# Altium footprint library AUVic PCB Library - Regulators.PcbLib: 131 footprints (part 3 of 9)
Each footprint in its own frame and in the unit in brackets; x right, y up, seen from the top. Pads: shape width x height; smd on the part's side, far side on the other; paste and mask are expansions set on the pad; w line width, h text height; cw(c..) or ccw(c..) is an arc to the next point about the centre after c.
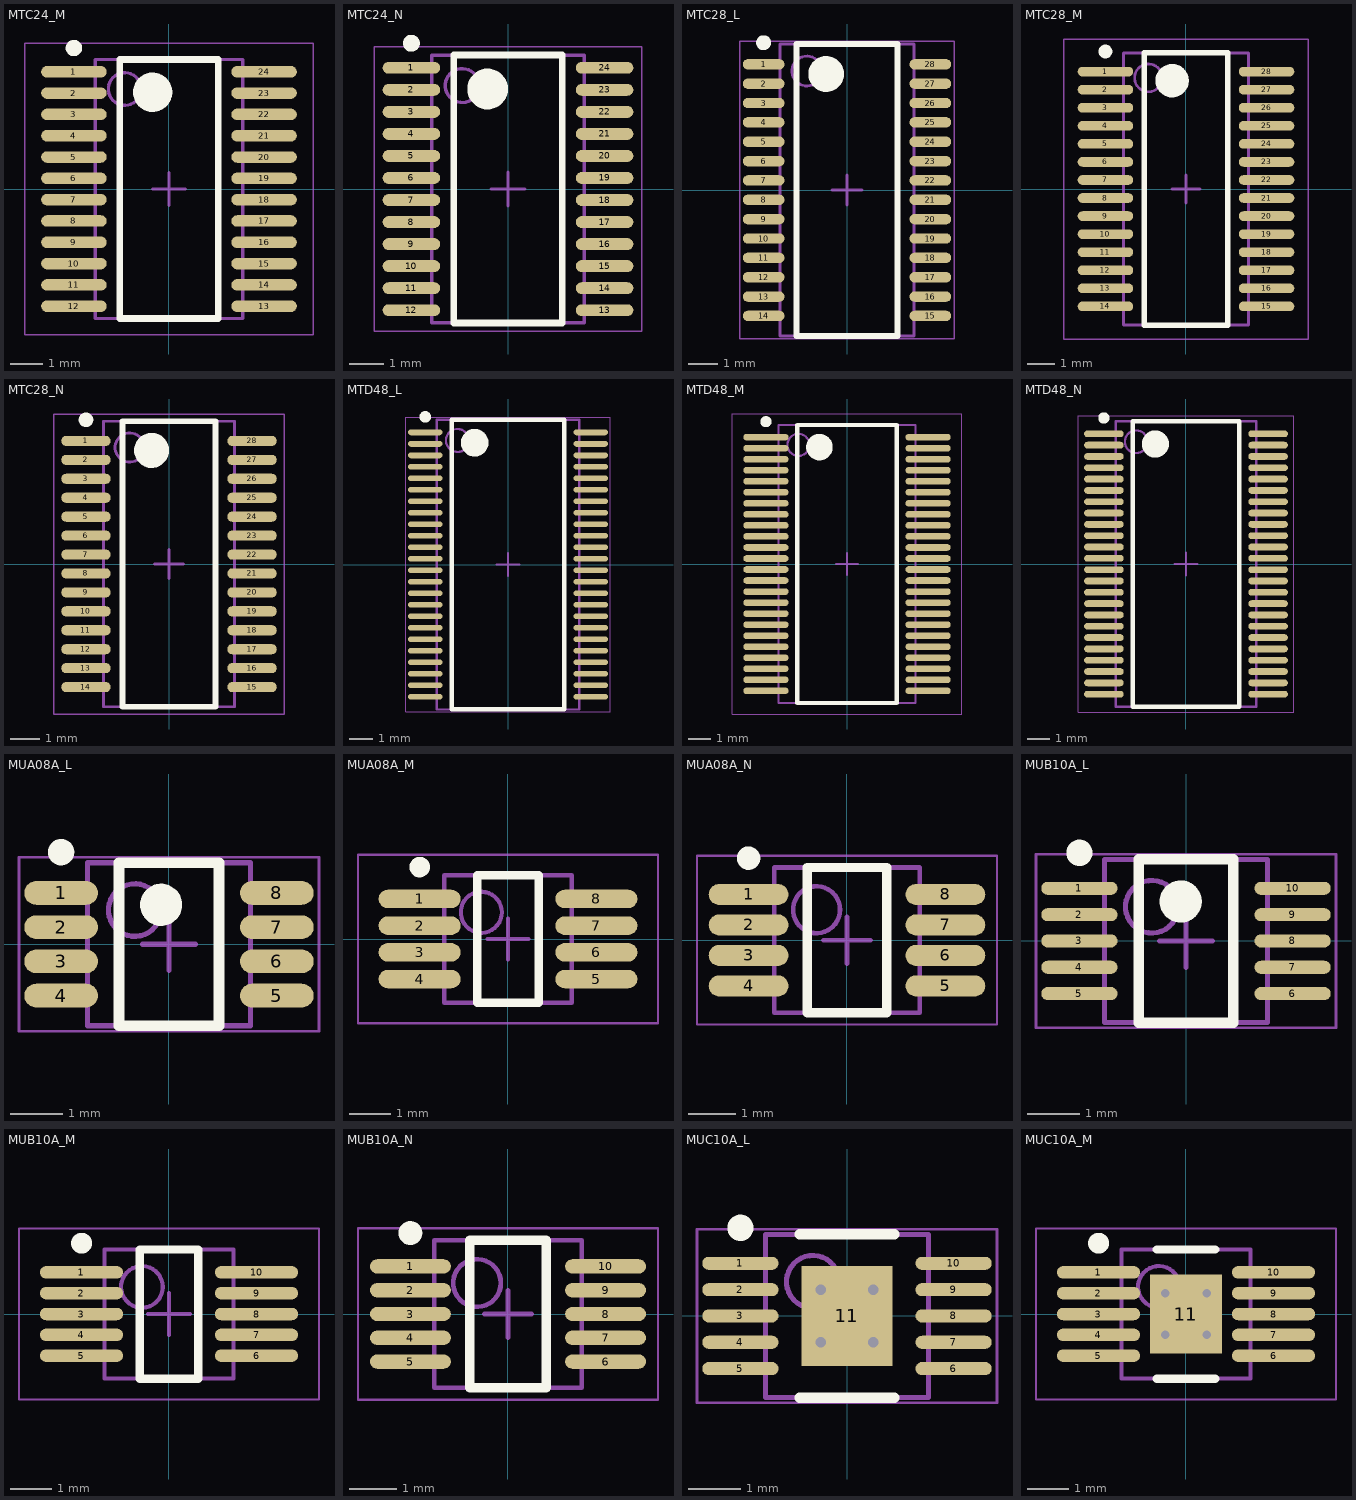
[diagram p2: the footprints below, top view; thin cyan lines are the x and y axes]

## MTC24_M [mm] "TSOP, 24-Leads, Body 7.8x4.4mm, Pitch 0.65mm, IPC Low Density"
height 1.1
pads (24):
  oval 2x0.35 smd: 1(-2.9,3.575) 2(-2.9,2.925) 3(-2.9,2.275) 4(-2.9,1.625) 5(-2.9,0.975) 6(-2.9,0.325) 7(-2.9,-0.325) 8(-2.9,-0.975) 9(-2.9,-1.625) 10(-2.9,-2.275) 11(-2.9,-2.925) 12(-2.9,-3.575) 13(2.9,-3.575) 14(2.9,-2.925) 15(2.9,-2.275) 16(2.9,-1.625) 17(2.9,-0.975) 18(2.9,-0.325) 19(2.9,0.325) 20(2.9,0.975) 21(2.9,1.625) 22(2.9,2.275) 23(2.9,2.925) 24(2.9,3.575)
Top Overlay:
  circle w0.6: c-0.5,2.95 r0.3
  circle w0.25: c-2.9,4.3 r0.125
  lines w0.2: -1.5,-3.95 1.5,-3.95 1.5,3.95 -1.5,3.95 -1.5,-3.95
Mechanical 13:
  circle w0.1: c-1.35,3.05 r0.5
  lines w0.1: -2.25,-3.95 2.25,-3.95 2.25,3.95 -2.25,3.95 -2.25,-3.95
Mechanical 15:
  lines w0.05: -4.4,-4.45 4.4,-4.45 4.4,4.45 -4.4,4.45 -4.4,-4.45
  lines w0.1: -0.5,0 0.5,0 ; 0,-0.5 0,0.5
3D body: height 1.1, standoff 0.05, extent -2.25,-3.95 2.25,3.95

## MTC24_N [mm] "TSOP, 24-Leads, Body 7.8x4.4mm, Pitch 0.65mm, IPC Medium Density"
height 1.1
pads (24):
  oval 1.7x0.35 smd: 1(-2.85,3.575) 2(-2.85,2.925) 3(-2.85,2.275) 4(-2.85,1.625) 5(-2.85,0.975) 6(-2.85,0.325) 7(-2.85,-0.325) 8(-2.85,-0.975) 9(-2.85,-1.625) 10(-2.85,-2.275) 11(-2.85,-2.925) 12(-2.85,-3.575) 13(2.85,-3.575) 14(2.85,-2.925) 15(2.85,-2.275) 16(2.85,-1.625) 17(2.85,-0.975) 18(2.85,-0.325) 19(2.85,0.325) 20(2.85,0.975) 21(2.85,1.625) 22(2.85,2.275) 23(2.85,2.925) 24(2.85,3.575)
Top Overlay:
  circle w0.6: c-0.6,2.95 r0.3
  circle w0.25: c-2.85,4.3 r0.125
  lines w0.2: -1.6,-3.95 1.6,-3.95 1.6,3.95 -1.6,3.95 -1.6,-3.95
Mechanical 13:
  circle w0.1: c-1.35,3.05 r0.5
  lines w0.1: -2.25,-3.95 2.25,-3.95 2.25,3.95 -2.25,3.95 -2.25,-3.95
Mechanical 15:
  lines w0.05: -3.95,-4.2 3.95,-4.2 3.95,4.2 -3.95,4.2 -3.95,-4.2
  lines w0.1: -0.5,0 0.5,0 ; 0,-0.5 0,0.5
3D body: height 1.1, standoff 0.05, extent -2.25,-3.95 2.25,3.95

## MTC28_L [mm] "TSOP, 28-Leads, Body 9.7x4.4mm, Pitch 0.65mm, IPC High Density"
height 1.1
pads (28):
  oval 1.4x0.35 smd: 1(-2.8,4.225) 2(-2.8,3.575) 3(-2.8,2.925) 4(-2.8,2.275) 5(-2.8,1.625) 6(-2.8,0.975) 7(-2.8,0.325) 8(-2.8,-0.325) 9(-2.8,-0.975) 10(-2.8,-1.625) 11(-2.8,-2.275) 12(-2.8,-2.925) 13(-2.8,-3.575) 14(-2.8,-4.225) 15(2.8,-4.225) 16(2.8,-3.575) 17(2.8,-2.925) 18(2.8,-2.275) 19(2.8,-1.625) 20(2.8,-0.975) 21(2.8,-0.325) 22(2.8,0.325) 23(2.8,0.975) 24(2.8,1.625) 25(2.8,2.275) 26(2.8,2.925) 27(2.8,3.575) 28(2.8,4.225)
Top Overlay:
  circle w0.25: c-2.8,4.95 r0.125
  circle w0.6: c-0.7,3.9 r0.3
  lines w0.2: -1.7,-4.9 -1.7,4.9 1.7,4.9 1.7,-4.9 -1.7,-4.9
Mechanical 13:
  circle w0.1: c-1.35,4 r0.5
  lines w0.1: -2.25,-4.9 -2.25,4.9 2.25,4.9 2.25,-4.9 -2.25,-4.9
Mechanical 15:
  lines w0.05: -3.6,-5 -3.6,5 3.6,5 3.6,-5 -3.6,-5
  lines w0.1: -0.5,0 0.5,0 ; 0,-0.5 0,0.5
3D body: height 1.1, standoff 0.05, extent -2.25,-4.9 2.25,4.9

## MTC28_M [mm] "TSOP, 28-Leads, Body 9.7x4.4mm, Pitch 0.65mm, IPC Low Density"
height 1.1
pads (28):
  oval 2x0.35 smd: 1(-2.9,4.225) 2(-2.9,3.575) 3(-2.9,2.925) 4(-2.9,2.275) 5(-2.9,1.625) 6(-2.9,0.975) 7(-2.9,0.325) 8(-2.9,-0.325) 9(-2.9,-0.975) 10(-2.9,-1.625) 11(-2.9,-2.275) 12(-2.9,-2.925) 13(-2.9,-3.575) 14(-2.9,-4.225) 15(2.9,-4.225) 16(2.9,-3.575) 17(2.9,-2.925) 18(2.9,-2.275) 19(2.9,-1.625) 20(2.9,-0.975) 21(2.9,-0.325) 22(2.9,0.325) 23(2.9,0.975) 24(2.9,1.625) 25(2.9,2.275) 26(2.9,2.925) 27(2.9,3.575) 28(2.9,4.225)
Top Overlay:
  circle w0.25: c-2.9,4.95 r0.125
  circle w0.6: c-0.5,3.9 r0.3
  lines w0.2: -1.5,-4.9 -1.5,4.9 1.5,4.9 1.5,-4.9 -1.5,-4.9
Mechanical 13:
  circle w0.1: c-1.35,4 r0.5
  lines w0.1: -2.25,-4.9 -2.25,4.9 2.25,4.9 2.25,-4.9 -2.25,-4.9
Mechanical 15:
  lines w0.05: -4.4,-5.4 -4.4,5.4 4.4,5.4 4.4,-5.4 -4.4,-5.4
  lines w0.1: -0.5,0 0.5,0 ; 0,-0.5 0,0.5
3D body: height 1.1, standoff 0.05, extent -2.25,-4.9 2.25,4.9

## MTC28_N [mm] "TSOP, 28-Leads, Body 9.7x4.4mm, Pitch 0.65mm, IPC Medium Density"
height 1.1
pads (28):
  oval 1.7x0.35 smd: 1(-2.85,4.225) 2(-2.85,3.575) 3(-2.85,2.925) 4(-2.85,2.275) 5(-2.85,1.625) 6(-2.85,0.975) 7(-2.85,0.325) 8(-2.85,-0.325) 9(-2.85,-0.975) 10(-2.85,-1.625) 11(-2.85,-2.275) 12(-2.85,-2.925) 13(-2.85,-3.575) 14(-2.85,-4.225) 15(2.85,-4.225) 16(2.85,-3.575) 17(2.85,-2.925) 18(2.85,-2.275) 19(2.85,-1.625) 20(2.85,-0.975) 21(2.85,-0.325) 22(2.85,0.325) 23(2.85,0.975) 24(2.85,1.625) 25(2.85,2.275) 26(2.85,2.925) 27(2.85,3.575) 28(2.85,4.225)
Top Overlay:
  circle w0.25: c-2.85,4.95 r0.125
  circle w0.6: c-0.6,3.9 r0.3
  lines w0.2: -1.6,-4.9 -1.6,4.9 1.6,4.9 1.6,-4.9 -1.6,-4.9
Mechanical 13:
  circle w0.1: c-1.35,4 r0.5
  lines w0.1: -2.25,-4.9 -2.25,4.9 2.25,4.9 2.25,-4.9 -2.25,-4.9
Mechanical 15:
  lines w0.05: -3.95,-5.15 -3.95,5.15 3.95,5.15 3.95,-5.15 -3.95,-5.15
  lines w0.1: -0.5,0 0.5,0 ; 0,-0.5 0,0.5
3D body: height 1.1, standoff 0.05, extent -2.25,-4.9 2.25,4.9

## MTD48_L [mm] "TSSOP, 48-Leads, Body 12.5x6.1mm, Pitch 0.5mm, IPC High Density"
height 1.1
pads (48):
  oval 1.5x0.25 smd: 1(-3.6,5.75) 2(-3.6,5.25) 3(-3.6,4.75) 4(-3.6,4.25) 5(-3.6,3.75) 6(-3.6,3.25) 7(-3.6,2.75) 8(-3.6,2.25) 9(-3.6,1.75) 10(-3.6,1.25) 11(-3.6,0.75) 12(-3.6,0.25) 13(-3.6,-0.25) 14(-3.6,-0.75) 15(-3.6,-1.25) 16(-3.6,-1.75) 17(-3.6,-2.25) 18(-3.6,-2.75) 19(-3.6,-3.25) 20(-3.6,-3.75) 21(-3.6,-4.25) 22(-3.6,-4.75) 23(-3.6,-5.25) 24(-3.6,-5.75) 25(3.6,-5.75) 26(3.6,-5.25) 27(3.6,-4.75) 28(3.6,-4.25) 29(3.6,-3.75) 30(3.6,-3.25) 31(3.6,-2.75) 32(3.6,-2.25) 33(3.6,-1.75) 34(3.6,-1.25) 35(3.6,-0.75) 36(3.6,-0.25) 37(3.6,0.25) 38(3.6,0.75) 39(3.6,1.25) 40(3.6,1.75) 41(3.6,2.25) 42(3.6,2.75) 43(3.6,3.25) 44(3.6,3.75) 45(3.6,4.25) 46(3.6,4.75) 47(3.6,5.25) 48(3.6,5.75)
Top Overlay:
  circle w0.6: c-1.45,5.3 r0.3
  circle w0.25: c-3.6,6.425 r0.125
  lines w0.2: -2.45,-6.3 2.45,-6.3 2.45,6.3 -2.45,6.3 -2.45,-6.3
Mechanical 13:
  circle w0.1: c-2.2,5.4 r0.5
  lines w0.1: -3.1,-6.3 3.1,-6.3 3.1,6.3 -3.1,6.3 -3.1,-6.3
Mechanical 15:
  lines w0.05: -4.45,-6.4 4.45,-6.4 4.45,6.4 -4.45,6.4 -4.45,-6.4
  lines w0.1: -0.5,0 0.5,0 ; 0,-0.5 0,0.5
3D body: height 1.1, standoff 0.05, extent -3.1,-6.3 3.1,6.3

## MTD48_M [mm] "TSSOP, 48-Leads, Body 12.5x6.1mm, Pitch 0.5mm, IPC Low Density"
height 1.1
pads (48):
  oval 2.05x0.3 smd: 1(-3.675,5.75) 2(-3.675,5.25) 3(-3.675,4.75) 4(-3.675,4.25) 5(-3.675,3.75) 6(-3.675,3.25) 7(-3.675,2.75) 8(-3.675,2.25) 9(-3.675,1.75) 10(-3.675,1.25) 11(-3.675,0.75) 12(-3.675,0.25) 13(-3.675,-0.25) 14(-3.675,-0.75) 15(-3.675,-1.25) 16(-3.675,-1.75) 17(-3.675,-2.25) 18(-3.675,-2.75) 19(-3.675,-3.25) 20(-3.675,-3.75) 21(-3.675,-4.25) 22(-3.675,-4.75) 23(-3.675,-5.25) 24(-3.675,-5.75) 25(3.675,-5.75) 26(3.675,-5.25) 27(3.675,-4.75) 28(3.675,-4.25) 29(3.675,-3.75) 30(3.675,-3.25) 31(3.675,-2.75) 32(3.675,-2.25) 33(3.675,-1.75) 34(3.675,-1.25) 35(3.675,-0.75) 36(3.675,-0.25) 37(3.675,0.25) 38(3.675,0.75) 39(3.675,1.25) 40(3.675,1.75) 41(3.675,2.25) 42(3.675,2.75) 43(3.675,3.25) 44(3.675,3.75) 45(3.675,4.25) 46(3.675,4.75) 47(3.675,5.25) 48(3.675,5.75)
Top Overlay:
  circle w0.6: c-1.25,5.3 r0.3
  circle w0.25: c-3.675,6.45 r0.125
  lines w0.2: -2.25,-6.3 2.25,-6.3 2.25,6.3 -2.25,6.3 -2.25,-6.3
Mechanical 13:
  circle w0.1: c-2.2,5.4 r0.5
  lines w0.1: -3.1,-6.3 3.1,-6.3 3.1,6.3 -3.1,6.3 -3.1,-6.3
Mechanical 15:
  lines w0.05: -5.2,-6.8 5.2,-6.8 5.2,6.8 -5.2,6.8 -5.2,-6.8
  lines w0.1: -0.5,0 0.5,0 ; 0,-0.5 0,0.5
3D body: height 1.1, standoff 0.05, extent -3.1,-6.3 3.1,6.3

## MTD48_N [mm] "TSSOP, 48-Leads, Body 12.5x6.1mm, Pitch 0.5mm, IPC Medium Density"
height 1.1
pads (48):
  oval 1.75x0.3 smd: 1(-3.625,5.75) 2(-3.625,5.25) 3(-3.625,4.75) 4(-3.625,4.25) 5(-3.625,3.75) 6(-3.625,3.25) 7(-3.625,2.75) 8(-3.625,2.25) 9(-3.625,1.75) 10(-3.625,1.25) 11(-3.625,0.75) 12(-3.625,0.25) 13(-3.625,-0.25) 14(-3.625,-0.75) 15(-3.625,-1.25) 16(-3.625,-1.75) 17(-3.625,-2.25) 18(-3.625,-2.75) 19(-3.625,-3.25) 20(-3.625,-3.75) 21(-3.625,-4.25) 22(-3.625,-4.75) 23(-3.625,-5.25) 24(-3.625,-5.75) 25(3.625,-5.75) 26(3.625,-5.25) 27(3.625,-4.75) 28(3.625,-4.25) 29(3.625,-3.75) 30(3.625,-3.25) 31(3.625,-2.75) 32(3.625,-2.25) 33(3.625,-1.75) 34(3.625,-1.25) 35(3.625,-0.75) 36(3.625,-0.25) 37(3.625,0.25) 38(3.625,0.75) 39(3.625,1.25) 40(3.625,1.75) 41(3.625,2.25) 42(3.625,2.75) 43(3.625,3.25) 44(3.625,3.75) 45(3.625,4.25) 46(3.625,4.75) 47(3.625,5.25) 48(3.625,5.75)
Top Overlay:
  circle w0.6: c-1.35,5.3 r0.3
  circle w0.25: c-3.625,6.45 r0.125
  lines w0.2: -2.35,-6.3 2.35,-6.3 2.35,6.3 -2.35,6.3 -2.35,-6.3
Mechanical 13:
  circle w0.1: c-2.2,5.4 r0.5
  lines w0.1: -3.1,-6.3 3.1,-6.3 3.1,6.3 -3.1,6.3 -3.1,-6.3
Mechanical 15:
  lines w0.05: -4.75,-6.55 4.75,-6.55 4.75,6.55 -4.75,6.55 -4.75,-6.55
  lines w0.1: -0.5,0 0.5,0 ; 0,-0.5 0,0.5
3D body: height 1.1, standoff 0.05, extent -3.1,-6.3 3.1,6.3

## MUA08A_L [mm] "TSOP, 8-Leads, Body 3x3mm, Pitch 0.65mm, IPC High Density"
height 1.09
pads (8):
  oval 1.4x0.45 smd: 1(-2.05,0.975) 2(-2.05,0.325) 3(-2.05,-0.325) 4(-2.05,-0.975) 5(2.05,-0.975) 6(2.05,-0.325) 7(2.05,0.325) 8(2.05,0.975)
Top Overlay:
  circle w0.25: c-2.05,1.75 r0.125
  circle w0.4: c-0.15,0.75 r0.2
  lines w0.2: -0.95,-1.55 -0.95,1.55 0.95,1.55 0.95,-1.55 -0.95,-1.55
Mechanical 13:
  circle w0.1: c-0.65,0.65 r0.5
  lines w0.1: -1.55,-1.55 -1.55,1.55 1.55,1.55 1.55,-1.55 -1.55,-1.55
Mechanical 15:
  lines w0.05: -2.85,-1.65 -2.85,1.65 2.85,1.65 2.85,-1.65 -2.85,-1.65
  lines w0.1: -0.5,0 0.5,0 ; 0,-0.5 0,0.5
3D body: height 1.09, standoff 0.06, extent -1.55,-1.55 1.55,1.55

## MUA08A_M [mm] "TSOP, 8-Leads, Body 3x3mm, Pitch 0.65mm, IPC Low Density"
height 1.09
pads (8):
  oval 2x0.45 smd: 1(-2.15,0.975) 2(-2.15,0.325) 3(-2.15,-0.325) 4(-2.15,-0.975) 5(2.15,-0.975) 6(2.15,-0.325) 7(2.15,0.325) 8(2.15,0.975)
Top Overlay:
  circle w0.25: c-2.15,1.75 r0.125
  lines w0.2: -0.75,-1.55 0.75,-1.55 0.75,1.55 -0.75,1.55 -0.75,-1.55
Mechanical 13:
  circle w0.1: c-0.65,0.65 r0.5
  lines w0.1: -1.55,-1.55 1.55,-1.55 1.55,1.55 -1.55,1.55 -1.55,-1.55
Mechanical 15:
  lines w0.05: -3.65,-2.05 3.65,-2.05 3.65,2.05 -3.65,2.05 -3.65,-2.05
  lines w0.1: -0.5,0 0.5,0 ; 0,-0.5 0,0.5
3D body: height 1.09, standoff 0.06, extent -1.55,-1.55 1.55,1.55

## MUA08A_N [mm] "TSOP, 8-Leads, Body 3x3mm, Pitch 0.65mm, IPC Medium Density"
height 1.09
pads (8):
  oval 1.7x0.45 smd: 1(-2.1,0.975) 2(-2.1,0.325) 3(-2.1,-0.325) 4(-2.1,-0.975) 5(2.1,-0.975) 6(2.1,-0.325) 7(2.1,0.325) 8(2.1,0.975)
Top Overlay:
  circle w0.25: c-2.1,1.75 r0.125
  lines w0.2: -0.85,-1.55 -0.85,1.55 0.85,1.55 0.85,-1.55 -0.85,-1.55
Mechanical 13:
  circle w0.1: c-0.65,0.65 r0.5
  lines w0.1: -1.55,-1.55 -1.55,1.55 1.55,1.55 1.55,-1.55 -1.55,-1.55
Mechanical 15:
  lines w0.05: -3.2,-1.8 -3.2,1.8 3.2,1.8 3.2,-1.8 -3.2,-1.8
  lines w0.1: -0.5,0 0.5,0 ; 0,-0.5 0,0.5
3D body: height 1.09, standoff 0.06, extent -1.55,-1.55 1.55,1.55

## MUB10A_L [mm] "TSSOP, 10-Leads, Body 3x3mm, Pitch 0.5mm, IPC High Density"
height 1.09
pads (10):
  oval 1.45x0.25 smd: 1(-2.025,1) 2(-2.025,0.5) 3(-2.025,0) 4(-2.025,-0.5) 5(-2.025,-1) 6(2.025,-1) 7(2.025,-0.5) 8(2.025,0) 9(2.025,0.5) 10(2.025,1)
Top Overlay:
  circle w0.4: c-0.1,0.75 r0.2
  circle w0.25: c-2.025,1.675 r0.125
  lines w0.2: -0.9,-1.55 0.9,-1.55 0.9,1.55 -0.9,1.55 -0.9,-1.55
Mechanical 13:
  circle w0.1: c-0.65,0.65 r0.5
  lines w0.1: -1.55,-1.55 1.55,-1.55 1.55,1.55 -1.55,1.55 -1.55,-1.55
Mechanical 15:
  lines w0.05: -2.85,-1.65 2.85,-1.65 2.85,1.65 -2.85,1.65 -2.85,-1.65
  lines w0.1: -0.5,0 0.5,0 ; 0,-0.5 0,0.5
3D body: height 1.09, standoff 0.06, extent -1.55,-1.55 1.55,1.55

## MUB10A_M [mm] "TSSOP, 10-Leads, Body 3x3mm, Pitch 0.5mm, IPC Low Density"
height 1.09
pads (10):
  oval 2x0.3 smd: 1(-2.1,1) 2(-2.1,0.5) 3(-2.1,0) 4(-2.1,-0.5) 5(-2.1,-1) 6(2.1,-1) 7(2.1,-0.5) 8(2.1,0) 9(2.1,0.5) 10(2.1,1)
Top Overlay:
  circle w0.25: c-2.1,1.7 r0.125
  lines w0.2: -0.7,-1.55 0.7,-1.55 0.7,1.55 -0.7,1.55 -0.7,-1.55
Mechanical 13:
  circle w0.1: c-0.65,0.65 r0.5
  lines w0.1: -1.55,-1.55 1.55,-1.55 1.55,1.55 -1.55,1.55 -1.55,-1.55
Mechanical 15:
  lines w0.05: -3.6,-2.05 3.6,-2.05 3.6,2.05 -3.6,2.05 -3.6,-2.05
  lines w0.1: -0.5,0 0.5,0 ; 0,-0.5 0,0.5
3D body: height 1.09, standoff 0.06, extent -1.55,-1.55 1.55,1.55

## MUB10A_N [mm] "TSSOP, 10-Leads, Body 3x3mm, Pitch 0.5mm, IPC Medium Density"
height 1.09
pads (10):
  oval 1.7x0.3 smd: 1(-2.05,1) 2(-2.05,0.5) 3(-2.05,0) 4(-2.05,-0.5) 5(-2.05,-1) 6(2.05,-1) 7(2.05,-0.5) 8(2.05,0) 9(2.05,0.5) 10(2.05,1)
Top Overlay:
  circle w0.25: c-2.05,1.7 r0.125
  lines w0.2: -0.8,-1.55 0.8,-1.55 0.8,1.55 -0.8,1.55 -0.8,-1.55
Mechanical 13:
  circle w0.1: c-0.65,0.65 r0.5
  lines w0.1: -1.55,-1.55 1.55,-1.55 1.55,1.55 -1.55,1.55 -1.55,-1.55
Mechanical 15:
  lines w0.05: -3.15,-1.8 3.15,-1.8 3.15,1.8 -3.15,1.8 -3.15,-1.8
  lines w0.1: -0.5,0 0.5,0 ; 0,-0.5 0,0.5
3D body: height 1.09, standoff 0.06, extent -1.55,-1.55 1.55,1.55

## MUC10A_L [mm] "TSSOP, 10-Leads, Body 3x3mm, Pitch 0.5mm, Exposed Pad, IPC High Density"
height 1.1
pads (11):
  oval 1.45x0.25 smd: 1(-2.025,1) 2(-2.025,0.5) 3(-2.025,0) 4(-2.025,-0.5) 5(-2.025,-1) 6(2.025,-1) 7(2.025,-0.5) 8(2.025,0) 9(2.025,0.5) 10(2.025,1)
  rect 1.73x1.9 smd: 11(0,0)
via -0.5,0.5 diameter 0.4 hole 0.2
via 0.5,0.5 diameter 0.4 hole 0.2
via -0.5,-0.5 diameter 0.4 hole 0.2
via 0.5,-0.5 diameter 0.4 hole 0.2
Top Overlay:
  circle w0.25: c-2.025,1.675 r0.125
  lines w0.2: -0.9,-1.55 0.9,-1.55 ; -0.9,1.55 0.9,1.55
Mechanical 13:
  circle w0.1: c-0.65,0.65 r0.5
  lines w0.1: -1.55,-1.55 1.55,-1.55 1.55,1.55 -1.55,1.55 -1.55,-1.55
Mechanical 15:
  lines w0.05: -2.85,-1.65 2.85,-1.65 2.85,1.65 -2.85,1.65 -2.85,-1.65
  lines w0.1: -0.5,0 0.5,0 ; 0,-0.5 0,0.5
3D body: height 1.1, standoff 0.05, extent -1.55,-1.55 1.55,1.55

## MUC10A_M [mm] "TSSOP, 10-Leads, Body 3x3mm, Pitch 0.5mm, Exposed Pad, IPC Low Density"
height 1.1
pads (11):
  oval 2x0.3 smd: 1(-2.1,1) 2(-2.1,0.5) 3(-2.1,0) 4(-2.1,-0.5) 5(-2.1,-1) 6(2.1,-1) 7(2.1,-0.5) 8(2.1,0) 9(2.1,0.5) 10(2.1,1)
  rect 1.73x1.9 smd: 11(0,0)
via -0.5,0.5 diameter 0.4 hole 0.2
via 0.5,0.5 diameter 0.4 hole 0.2
via -0.5,-0.5 diameter 0.4 hole 0.2
via 0.5,-0.5 diameter 0.4 hole 0.2
Top Overlay:
  circle w0.25: c-2.1,1.7 r0.125
  lines w0.2: -0.7,-1.55 0.7,-1.55 ; -0.7,1.55 0.7,1.55
Mechanical 13:
  circle w0.1: c-0.65,0.65 r0.5
  lines w0.1: -1.55,-1.55 1.55,-1.55 1.55,1.55 -1.55,1.55 -1.55,-1.55
Mechanical 15:
  lines w0.05: -3.6,-2.05 3.6,-2.05 3.6,2.05 -3.6,2.05 -3.6,-2.05
  lines w0.1: -0.5,0 0.5,0 ; 0,-0.5 0,0.5
3D body: height 1.1, standoff 0.05, extent -1.55,-1.55 1.55,1.55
